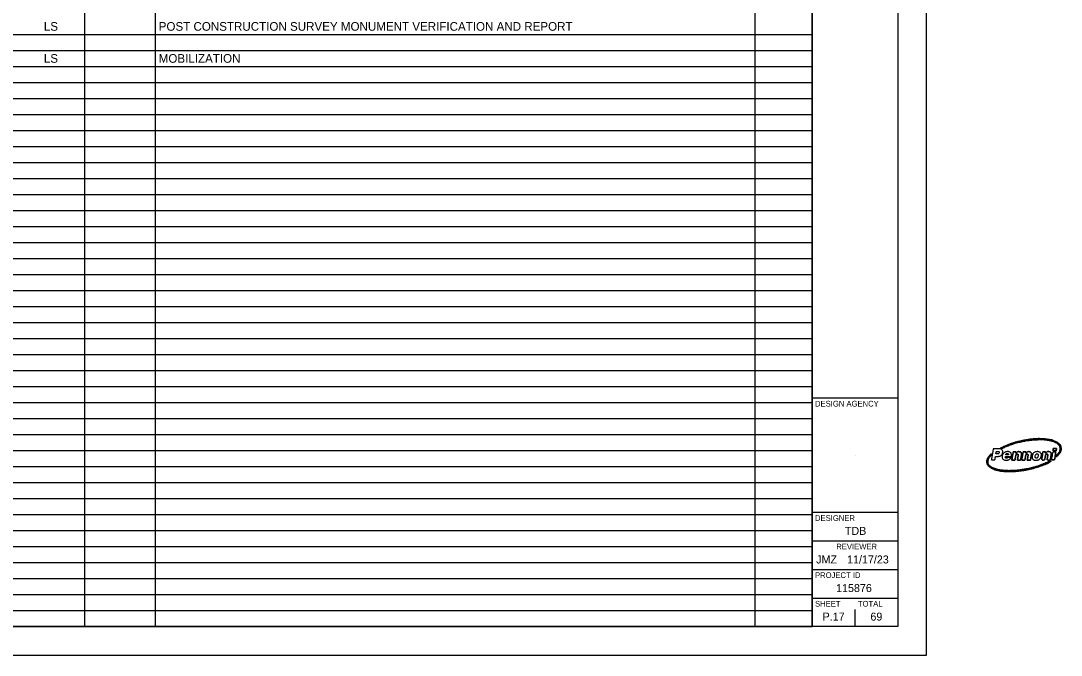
# Model space of a CAD drawing. Extents: x -50.3 to 36.4, y 0 to 22.5.
# Drawn here: x 18.16 to 36.36, y 0 to 11.1 of the extents above; entities that cross this region are included whole.
import ezdxf

# ---------------------------------------------------------------- set-up
doc = ezdxf.new("R2010")
doc.units = 0
for name, color, linetype in [('SH_Border', 7, 'Continuous'), ('SH_Cut_Line', 7, 'Continuous'), ('SH_Data', 7, 'Continuous'), ('SH_Text', 7, 'Continuous')]:
    doc.layers.add(name, color=color, linetype=linetype)

msp = doc.modelspace()

# ---------------------------------------------------------------- linework, layer by layer
at = {"layer": 'SH_Border'}
for p, q in [((32, 0.5), (32, 21.5)), ((32, 4.5), (33.5, 4.5)), ((35.435, 3.503), (35.385, 3.503)), ((32, 2.5), (33.5, 2.5)), ((32, 2), (33.5, 2)), ((32, 1.5), (33.5, 1.5)), ((32, 1), (33.5, 1))]:
    msp.add_line(p, q, dxfattribs=at)
msp.add_lwpolyline([(1.5, 21.5), (33.5, 21.5), (33.5, 0.5), (1.5, 0.5)], close=True, dxfattribs=at)
for points, degree in [([(35.294, 3.621), (35.301, 3.619), (35.307, 3.616), (35.313, 3.615), (35.315, 3.614), (35.318, 3.614), (35.32, 3.615), (35.349, 3.629), (35.377, 3.643), (35.406, 3.655), (35.447, 3.673), (35.49, 3.688), (35.532, 3.701), (35.574, 3.714), (35.617, 3.725), (35.66, 3.734), (35.7, 3.743), (35.74, 3.751), (35.78, 3.756), (35.812, 3.76), (35.844, 3.764), (35.876, 3.767), (35.901, 3.769), (35.927, 3.77), (35.952, 3.771), (36.007, 3.772), (36.062, 3.77), (36.116, 3.762), (36.146, 3.758), (36.175, 3.752), (36.204, 3.742), (36.239, 3.731), (36.273, 3.717), (36.301, 3.691), (36.316, 3.678), (36.328, 3.661), (36.333, 3.641), (36.338, 3.624), (36.339, 3.607), (36.336, 3.589), (36.333, 3.569), (36.323, 3.552), (36.311, 3.536), (36.298, 3.521), (36.284, 3.508), (36.27, 3.495), (36.268, 3.494), (36.267, 3.492), (36.266, 3.49), (36.265, 3.485), (36.264, 3.479), (36.263, 3.473), (36.263, 3.471), (36.262, 3.469), (36.262, 3.465), (36.286, 3.485), (36.308, 3.505), (36.327, 3.529), (36.336, 3.54), (36.344, 3.553), (36.349, 3.566), (36.356, 3.585), (36.356, 3.604), (36.354, 3.623), (36.35, 3.658), (36.334, 3.685), (36.308, 3.708), (36.284, 3.728), (36.256, 3.741), (36.227, 3.752), (36.19, 3.766), (36.152, 3.774), (36.112, 3.779), (36.078, 3.784), (36.042, 3.787), (36.007, 3.788), (35.951, 3.789), (35.895, 3.787), (35.838, 3.781), (35.807, 3.777), (35.777, 3.773), (35.746, 3.768), (35.701, 3.761), (35.656, 3.752), (35.611, 3.74), (35.551, 3.725), (35.492, 3.707), (35.433, 3.684), (35.392, 3.669), (35.352, 3.651), (35.313, 3.631), (35.307, 3.628), (35.301, 3.625), (35.294, 3.621)], 3), ([(35.294, 3.621), (35.301, 3.625), (35.307, 3.628), (35.313, 3.631), (35.352, 3.651), (35.392, 3.669), (35.433, 3.684), (35.492, 3.707), (35.551, 3.725), (35.611, 3.74), (35.656, 3.752), (35.701, 3.761), (35.746, 3.768), (35.777, 3.773), (35.807, 3.777), (35.838, 3.781), (35.895, 3.787), (35.951, 3.789), (36.007, 3.788), (36.042, 3.787), (36.078, 3.784), (36.112, 3.779), (36.152, 3.774), (36.19, 3.766), (36.227, 3.752), (36.256, 3.741), (36.284, 3.728), (36.308, 3.708), (36.334, 3.685), (36.35, 3.658), (36.354, 3.623), (36.356, 3.604), (36.356, 3.585), (36.349, 3.566), (36.344, 3.553), (36.336, 3.54), (36.327, 3.529), (36.308, 3.505), (36.286, 3.485), (36.262, 3.465), (36.262, 3.469), (36.263, 3.471), (36.263, 3.473), (36.264, 3.479), (36.265, 3.485), (36.266, 3.49), (36.267, 3.492), (36.268, 3.494), (36.27, 3.495), (36.284, 3.508), (36.298, 3.521), (36.311, 3.536), (36.323, 3.552), (36.333, 3.569), (36.336, 3.589), (36.339, 3.607), (36.338, 3.624), (36.333, 3.641), (36.328, 3.661), (36.316, 3.678), (36.301, 3.691), (36.273, 3.717), (36.239, 3.731), (36.204, 3.742), (36.175, 3.752), (36.146, 3.758), (36.116, 3.762), (36.062, 3.77), (36.007, 3.772), (35.952, 3.771), (35.927, 3.77), (35.901, 3.769), (35.876, 3.767), (35.844, 3.764), (35.812, 3.76), (35.78, 3.756), (35.74, 3.751), (35.7, 3.743), (35.66, 3.734), (35.617, 3.725), (35.574, 3.714), (35.532, 3.701), (35.49, 3.688), (35.447, 3.673), (35.406, 3.655), (35.377, 3.643), (35.349, 3.629), (35.32, 3.615), (35.318, 3.614), (35.315, 3.614), (35.313, 3.615), (35.307, 3.616), (35.301, 3.619), (35.294, 3.621)], 3), ([(36.182, 3.392), (36.182, 3.392), (36.182, 3.393), (36.182, 3.393), (36.172, 3.393), (36.162, 3.393), (36.152, 3.393), (36.15, 3.393), (36.147, 3.392), (36.145, 3.391), (36.107, 3.372), (36.069, 3.355), (36.03, 3.34), (35.972, 3.317), (35.913, 3.298), (35.853, 3.283), (35.81, 3.271), (35.767, 3.262), (35.723, 3.254), (35.698, 3.25), (35.673, 3.246), (35.648, 3.242), (35.623, 3.239), (35.597, 3.236), (35.571, 3.234), (35.547, 3.232), (35.523, 3.23), (35.499, 3.23), (35.471, 3.229), (35.443, 3.228), (35.414, 3.229), (35.383, 3.231), (35.352, 3.233), (35.322, 3.236), (35.284, 3.24), (35.246, 3.248), (35.209, 3.259), (35.178, 3.269), (35.148, 3.282), (35.121, 3.302), (35.104, 3.314), (35.09, 3.329), (35.081, 3.348), (35.069, 3.374), (35.07, 3.4), (35.081, 3.427), (35.09, 3.45), (35.104, 3.47), (35.121, 3.488), (35.126, 3.494), (35.132, 3.5), (35.132, 3.509), (35.132, 3.514), (35.134, 3.52), (35.135, 3.526), (35.134, 3.525), (35.133, 3.525), (35.132, 3.524), (35.123, 3.514), (35.113, 3.505), (35.104, 3.494), (35.084, 3.472), (35.068, 3.448), (35.06, 3.419), (35.055, 3.402), (35.054, 3.385), (35.057, 3.368), (35.062, 3.341), (35.076, 3.319), (35.096, 3.301), (35.119, 3.28), (35.146, 3.266), (35.174, 3.254), (35.221, 3.235), (35.27, 3.225), (35.321, 3.219), (35.351, 3.216), (35.382, 3.214), (35.413, 3.212), (35.456, 3.211), (35.498, 3.211), (35.54, 3.215), (35.575, 3.217), (35.609, 3.221), (35.643, 3.225), (35.674, 3.229), (35.704, 3.234), (35.735, 3.239), (35.789, 3.249), (35.843, 3.261), (35.896, 3.276), (35.941, 3.289), (35.986, 3.304), (36.029, 3.321), (36.073, 3.338), (36.115, 3.356), (36.156, 3.377), (36.165, 3.382), (36.173, 3.387), (36.182, 3.392)], 3), ([(36.182, 3.392), (36.173, 3.387), (36.165, 3.382), (36.156, 3.377), (36.115, 3.356), (36.073, 3.338), (36.029, 3.321), (35.986, 3.304), (35.941, 3.289), (35.896, 3.276), (35.843, 3.261), (35.789, 3.249), (35.735, 3.239), (35.704, 3.234), (35.674, 3.229), (35.643, 3.225), (35.609, 3.221), (35.575, 3.217), (35.54, 3.215), (35.498, 3.211), (35.456, 3.211), (35.413, 3.212), (35.382, 3.214), (35.351, 3.216), (35.321, 3.219), (35.27, 3.225), (35.221, 3.235), (35.174, 3.254), (35.146, 3.266), (35.119, 3.28), (35.096, 3.301), (35.076, 3.319), (35.062, 3.341), (35.057, 3.368), (35.054, 3.385), (35.055, 3.402), (35.06, 3.419), (35.068, 3.448), (35.084, 3.472), (35.104, 3.494), (35.113, 3.505), (35.123, 3.514), (35.132, 3.524), (35.133, 3.525), (35.134, 3.525), (35.135, 3.526), (35.134, 3.52), (35.132, 3.514), (35.132, 3.509), (35.132, 3.5), (35.126, 3.494), (35.121, 3.488), (35.104, 3.47), (35.09, 3.45), (35.081, 3.427), (35.07, 3.4), (35.069, 3.374), (35.081, 3.348), (35.09, 3.329), (35.104, 3.314), (35.121, 3.302), (35.148, 3.282), (35.178, 3.269), (35.209, 3.259), (35.246, 3.248), (35.284, 3.24), (35.322, 3.236), (35.352, 3.233), (35.383, 3.231), (35.414, 3.229), (35.443, 3.228), (35.471, 3.229), (35.499, 3.23), (35.523, 3.23), (35.547, 3.232), (35.571, 3.234), (35.597, 3.236), (35.623, 3.239), (35.648, 3.242), (35.673, 3.246), (35.698, 3.25), (35.723, 3.254), (35.767, 3.262), (35.81, 3.271), (35.853, 3.283), (35.913, 3.298), (35.972, 3.317), (36.03, 3.34), (36.069, 3.355), (36.107, 3.372), (36.145, 3.391), (36.147, 3.392), (36.15, 3.393), (36.152, 3.393), (36.162, 3.393), (36.172, 3.393), (36.182, 3.393), (36.182, 3.393), (36.182, 3.392), (36.182, 3.392)], 3), ([(35.305, 3.602), (35.293, 3.608), (35.279, 3.61), (35.266, 3.61), (35.234, 3.611), (35.202, 3.61), (35.171, 3.61), (35.168, 3.61), (35.167, 3.61), (35.167, 3.608), (35.163, 3.586), (35.16, 3.565), (35.156, 3.543), (35.15, 3.509), (35.144, 3.474), (35.138, 3.439), (35.136, 3.432), (35.135, 3.424), (35.134, 3.417)], 3), ([(35.134, 3.417), (35.135, 3.417), (35.135, 3.417), (35.136, 3.417), (35.155, 3.417), (35.175, 3.417), (35.194, 3.417), (35.197, 3.417), (35.197, 3.418), (35.197, 3.42), (35.199, 3.431), (35.201, 3.442), (35.203, 3.454), (35.204, 3.461), (35.206, 3.469), (35.207, 3.477)], 3), ([(35.207, 3.477), (35.215, 3.477), (35.222, 3.477), (35.229, 3.477), (35.242, 3.477), (35.254, 3.477), (35.267, 3.48), (35.284, 3.483), (35.299, 3.49), (35.311, 3.502), (35.326, 3.518), (35.332, 3.537), (35.332, 3.559), (35.333, 3.578), (35.324, 3.593), (35.305, 3.602)], 3), ([(35.215, 3.522), (35.217, 3.536), (35.22, 3.55), (35.222, 3.563), (35.222, 3.564), (35.224, 3.565), (35.224, 3.565), (35.236, 3.565), (35.247, 3.567), (35.259, 3.563), (35.269, 3.56), (35.273, 3.554), (35.271, 3.543)], 3), ([(35.271, 3.543), (35.268, 3.531), (35.26, 3.523), (35.247, 3.522), (35.237, 3.522), (35.226, 3.522), (35.215, 3.522)], 3), ([(35.487, 3.508), (35.483, 3.533), (35.47, 3.55), (35.446, 3.557), (35.433, 3.562), (35.419, 3.562), (35.406, 3.561), (35.384, 3.558), (35.365, 3.549), (35.349, 3.532), (35.335, 3.517), (35.327, 3.5), (35.325, 3.479), (35.322, 3.45), (35.334, 3.426), (35.363, 3.417), (35.379, 3.412), (35.395, 3.411), (35.412, 3.414), (35.429, 3.416), (35.446, 3.422), (35.46, 3.434), (35.467, 3.441), (35.474, 3.449), (35.478, 3.459)], 3), ([(35.478, 3.459), (35.461, 3.459), (35.444, 3.459), (35.427, 3.458), (35.426, 3.458), (35.425, 3.457), (35.424, 3.457), (35.42, 3.454), (35.416, 3.45), (35.411, 3.448), (35.395, 3.442), (35.378, 3.451), (35.379, 3.47), (35.379, 3.474), (35.38, 3.475), (35.384, 3.475), (35.416, 3.475), (35.448, 3.475), (35.48, 3.475), (35.482, 3.475), (35.484, 3.475), (35.486, 3.475)], 3), ([(35.385, 3.503), (35.386, 3.515), (35.395, 3.525), (35.408, 3.527), (35.414, 3.528), (35.42, 3.528), (35.425, 3.525), (35.433, 3.521), (35.436, 3.513), (35.435, 3.503)], 3), ([(35.486, 3.475), (35.488, 3.486), (35.489, 3.497), (35.487, 3.508)], 2), ([(35.493, 3.416), (35.493, 3.415), (35.494, 3.415), (35.494, 3.415), (35.511, 3.415), (35.528, 3.415), (35.545, 3.415), (35.548, 3.415), (35.548, 3.416), (35.549, 3.418), (35.55, 3.426), (35.551, 3.435), (35.553, 3.443), (35.556, 3.46), (35.559, 3.478), (35.563, 3.495), (35.565, 3.505), (35.569, 3.513), (35.579, 3.515), (35.592, 3.519), (35.606, 3.516), (35.604, 3.497), (35.602, 3.482), (35.599, 3.468), (35.597, 3.454), (35.595, 3.441), (35.592, 3.428), (35.59, 3.416), (35.591, 3.415), (35.591, 3.415), (35.592, 3.415), (35.609, 3.415), (35.626, 3.415), (35.643, 3.415), (35.645, 3.415), (35.646, 3.416), (35.646, 3.419), (35.65, 3.442), (35.654, 3.466), (35.659, 3.49), (35.661, 3.502), (35.663, 3.515), (35.661, 3.527), (35.659, 3.543), (35.65, 3.554), (35.634, 3.558), (35.612, 3.564), (35.593, 3.56), (35.576, 3.545), (35.572, 3.542), (35.568, 3.538), (35.564, 3.535), (35.565, 3.542), (35.567, 3.549), (35.568, 3.557), (35.552, 3.557), (35.535, 3.557), (35.519, 3.556), (35.518, 3.556), (35.517, 3.555), (35.517, 3.554), (35.516, 3.55), (35.515, 3.545), (35.514, 3.541), (35.509, 3.511), (35.504, 3.48), (35.498, 3.45), (35.496, 3.438), (35.495, 3.427), (35.493, 3.416)], 3), ([(35.493, 3.416), (35.495, 3.427), (35.496, 3.438), (35.498, 3.45), (35.504, 3.48), (35.509, 3.511), (35.514, 3.541), (35.515, 3.545), (35.516, 3.55), (35.517, 3.554), (35.517, 3.555), (35.518, 3.556), (35.519, 3.556), (35.535, 3.557), (35.552, 3.557), (35.568, 3.557), (35.567, 3.549), (35.565, 3.542), (35.564, 3.535), (35.568, 3.538), (35.572, 3.542), (35.576, 3.545), (35.593, 3.56), (35.612, 3.564), (35.634, 3.558), (35.65, 3.554), (35.659, 3.543), (35.661, 3.527), (35.663, 3.515), (35.661, 3.502), (35.659, 3.49), (35.654, 3.466), (35.65, 3.442), (35.646, 3.419), (35.646, 3.416), (35.645, 3.415), (35.643, 3.415), (35.626, 3.415), (35.609, 3.415), (35.592, 3.415), (35.591, 3.415), (35.591, 3.415), (35.59, 3.416), (35.592, 3.428), (35.595, 3.441), (35.597, 3.454), (35.599, 3.468), (35.602, 3.482), (35.604, 3.497), (35.606, 3.516), (35.592, 3.519), (35.579, 3.515), (35.569, 3.513), (35.565, 3.505), (35.563, 3.495), (35.559, 3.478), (35.556, 3.46), (35.553, 3.443), (35.551, 3.435), (35.55, 3.426), (35.549, 3.418), (35.548, 3.416), (35.548, 3.415), (35.545, 3.415), (35.528, 3.415), (35.511, 3.415), (35.494, 3.415), (35.494, 3.415), (35.493, 3.415), (35.493, 3.416)], 3), ([(35.666, 3.416), (35.666, 3.415), (35.666, 3.415), (35.667, 3.415), (35.684, 3.415), (35.701, 3.415), (35.719, 3.415), (35.72, 3.415), (35.721, 3.417), (35.721, 3.418), (35.725, 3.435), (35.727, 3.452), (35.731, 3.469), (35.732, 3.479), (35.734, 3.49), (35.737, 3.5), (35.741, 3.513), (35.753, 3.519), (35.766, 3.516), (35.772, 3.515), (35.775, 3.511), (35.776, 3.505), (35.777, 3.502), (35.777, 3.499), (35.777, 3.496), (35.775, 3.485), (35.773, 3.473), (35.771, 3.462), (35.768, 3.447), (35.766, 3.431), (35.763, 3.416), (35.763, 3.415), (35.764, 3.415), (35.764, 3.415), (35.781, 3.415), (35.799, 3.415), (35.816, 3.415), (35.817, 3.415), (35.819, 3.417), (35.819, 3.418), (35.823, 3.441), (35.827, 3.463), (35.831, 3.485), (35.833, 3.497), (35.835, 3.509), (35.835, 3.522), (35.835, 3.537), (35.829, 3.55), (35.813, 3.556), (35.793, 3.564), (35.773, 3.562), (35.755, 3.55), (35.749, 3.545), (35.743, 3.54), (35.737, 3.535), (35.739, 3.543), (35.74, 3.549), (35.741, 3.557), (35.724, 3.557), (35.709, 3.557), (35.693, 3.557), (35.69, 3.557), (35.69, 3.555), (35.69, 3.553), (35.685, 3.529), (35.681, 3.505), (35.677, 3.481), (35.673, 3.46), (35.669, 3.438), (35.666, 3.416)], 3), ([(35.666, 3.416), (35.669, 3.438), (35.673, 3.46), (35.677, 3.481), (35.681, 3.505), (35.685, 3.529), (35.69, 3.553), (35.69, 3.555), (35.69, 3.557), (35.693, 3.557), (35.709, 3.557), (35.724, 3.557), (35.741, 3.557), (35.74, 3.549), (35.739, 3.543), (35.737, 3.535), (35.743, 3.54), (35.749, 3.545), (35.755, 3.55), (35.773, 3.562), (35.793, 3.564), (35.813, 3.556), (35.829, 3.55), (35.835, 3.537), (35.835, 3.522), (35.835, 3.509), (35.833, 3.497), (35.831, 3.485), (35.827, 3.463), (35.823, 3.441), (35.819, 3.418), (35.819, 3.417), (35.817, 3.415), (35.816, 3.415), (35.799, 3.415), (35.781, 3.415), (35.764, 3.415), (35.764, 3.415), (35.763, 3.415), (35.763, 3.416), (35.766, 3.431), (35.768, 3.447), (35.771, 3.462), (35.773, 3.473), (35.775, 3.485), (35.777, 3.496), (35.777, 3.499), (35.777, 3.502), (35.776, 3.505), (35.775, 3.511), (35.772, 3.515), (35.766, 3.516), (35.753, 3.519), (35.741, 3.513), (35.737, 3.5), (35.734, 3.49), (35.732, 3.479), (35.731, 3.469), (35.727, 3.452), (35.725, 3.435), (35.721, 3.418), (35.721, 3.417), (35.72, 3.415), (35.719, 3.415), (35.701, 3.415), (35.684, 3.415), (35.667, 3.415), (35.666, 3.415), (35.666, 3.415), (35.666, 3.416)], 3), ([(36.009, 3.508), (36.007, 3.53), (35.996, 3.545), (35.976, 3.554), (35.957, 3.562), (35.937, 3.562), (35.917, 3.558), (35.893, 3.553), (35.873, 3.541), (35.86, 3.52), (35.859, 3.518), (35.858, 3.515), (35.857, 3.513), (35.856, 3.511), (35.855, 3.509), (35.854, 3.507), (35.849, 3.496), (35.846, 3.484), (35.846, 3.472), (35.846, 3.47), (35.846, 3.467), (35.846, 3.465), (35.846, 3.457), (35.848, 3.45), (35.851, 3.444), (35.851, 3.443), (35.852, 3.441), (35.852, 3.44), (35.853, 3.439), (35.853, 3.438), (35.854, 3.437), (35.856, 3.434), (35.859, 3.43), (35.863, 3.427), (35.864, 3.426), (35.867, 3.424), (35.869, 3.423), (35.869, 3.422), (35.87, 3.422), (35.87, 3.422), (35.872, 3.421), (35.873, 3.42), (35.874, 3.42), (35.876, 3.419), (35.878, 3.418), (35.88, 3.417), (35.891, 3.412), (35.902, 3.411), (35.914, 3.41)], 3), ([(35.902, 3.471), (35.902, 3.487), (35.905, 3.501), (35.914, 3.513), (35.919, 3.519), (35.926, 3.523), (35.934, 3.523), (35.943, 3.523), (35.949, 3.52), (35.951, 3.511), (35.952, 3.505), (35.953, 3.498), (35.952, 3.491)], 3), ([(35.952, 3.491), (35.952, 3.481), (35.949, 3.471), (35.944, 3.462), (35.938, 3.452), (35.928, 3.447), (35.917, 3.449), (35.911, 3.45), (35.906, 3.453), (35.904, 3.459), (35.903, 3.464), (35.902, 3.469), (35.902, 3.471)], 3), ([(35.914, 3.41), (35.922, 3.411), (35.929, 3.412), (35.936, 3.413), (35.955, 3.416), (35.972, 3.425), (35.985, 3.439), (36.002, 3.459), (36.01, 3.482), (36.009, 3.508)], 3), ([(36.036, 3.556), (36.028, 3.509), (36.02, 3.462), (36.012, 3.415), (36.031, 3.415), (36.049, 3.415), (36.067, 3.415), (36.07, 3.43), (36.072, 3.444), (36.075, 3.458), (36.077, 3.471), (36.079, 3.484), (36.082, 3.496), (36.085, 3.51), (36.095, 3.517), (36.108, 3.517), (36.117, 3.516), (36.122, 3.511), (36.123, 3.503), (36.123, 3.5), (36.123, 3.497), (36.123, 3.494), (36.119, 3.475), (36.116, 3.456), (36.113, 3.437), (36.112, 3.43), (36.11, 3.423), (36.109, 3.415), (36.128, 3.415), (36.146, 3.415), (36.164, 3.415), (36.165, 3.417), (36.165, 3.418), (36.165, 3.419), (36.169, 3.44), (36.173, 3.462), (36.176, 3.483), (36.179, 3.497), (36.182, 3.51), (36.181, 3.525), (36.18, 3.541), (36.171, 3.553), (36.155, 3.558), (36.13, 3.565), (36.108, 3.559), (36.09, 3.541), (36.088, 3.539), (36.086, 3.537), (36.084, 3.535), (36.084, 3.535), (36.084, 3.535), (36.083, 3.536), (36.085, 3.542), (36.086, 3.549), (36.087, 3.556), (36.07, 3.556), (36.053, 3.556), (36.036, 3.556)], 3), ([(36.036, 3.556), (36.053, 3.556), (36.07, 3.556), (36.087, 3.556), (36.086, 3.549), (36.085, 3.542), (36.083, 3.536), (36.084, 3.535), (36.084, 3.535), (36.084, 3.535), (36.086, 3.537), (36.088, 3.539), (36.09, 3.541), (36.108, 3.559), (36.13, 3.565), (36.155, 3.558), (36.171, 3.553), (36.18, 3.541), (36.181, 3.525), (36.182, 3.51), (36.179, 3.497), (36.176, 3.483), (36.173, 3.462), (36.169, 3.44), (36.165, 3.419), (36.165, 3.418), (36.165, 3.417), (36.164, 3.415), (36.146, 3.415), (36.128, 3.415), (36.109, 3.415), (36.11, 3.423), (36.112, 3.43), (36.113, 3.437), (36.116, 3.456), (36.119, 3.475), (36.123, 3.494), (36.123, 3.497), (36.123, 3.5), (36.123, 3.503), (36.122, 3.511), (36.117, 3.516), (36.108, 3.517), (36.095, 3.517), (36.085, 3.51), (36.082, 3.496), (36.079, 3.484), (36.077, 3.471), (36.075, 3.458), (36.072, 3.444), (36.07, 3.43), (36.067, 3.415), (36.049, 3.415), (36.031, 3.415), (36.012, 3.415), (36.02, 3.462), (36.028, 3.509), (36.036, 3.556)], 3), ([(36.239, 3.417), (36.221, 3.417), (36.203, 3.417), (36.184, 3.417), (36.192, 3.464), (36.2, 3.51), (36.208, 3.557), (36.227, 3.557), (36.245, 3.557), (36.264, 3.557), (36.255, 3.51), (36.247, 3.464), (36.239, 3.417)], 3), ([(36.239, 3.417), (36.247, 3.464), (36.255, 3.51), (36.264, 3.557), (36.245, 3.557), (36.227, 3.557), (36.208, 3.557), (36.2, 3.51), (36.192, 3.464), (36.184, 3.417), (36.203, 3.417), (36.221, 3.417), (36.239, 3.417)], 3), ([(36.274, 3.615), (36.272, 3.603), (36.27, 3.591), (36.267, 3.578), (36.267, 3.577), (36.265, 3.576), (36.264, 3.576), (36.247, 3.576), (36.23, 3.576), (36.212, 3.576), (36.213, 3.586), (36.215, 3.595), (36.217, 3.604), (36.217, 3.606), (36.218, 3.609), (36.218, 3.611), (36.218, 3.615), (36.219, 3.615), (36.223, 3.615), (36.238, 3.615), (36.254, 3.615), (36.269, 3.615), (36.271, 3.615), (36.272, 3.615), (36.274, 3.615)], 3), ([(36.274, 3.615), (36.272, 3.615), (36.271, 3.615), (36.269, 3.615), (36.254, 3.615), (36.238, 3.615), (36.223, 3.615), (36.219, 3.615), (36.218, 3.615), (36.218, 3.611), (36.218, 3.609), (36.217, 3.606), (36.217, 3.604), (36.215, 3.595), (36.213, 3.586), (36.212, 3.576), (36.23, 3.576), (36.247, 3.576), (36.264, 3.576), (36.265, 3.576), (36.267, 3.577), (36.267, 3.578), (36.27, 3.591), (36.272, 3.603), (36.274, 3.615)], 3)]:
    msp.add_open_spline(points, degree=degree, dxfattribs=at)
at = {"layer": 'SH_Cut_Line'}
msp.add_lwpolyline([(0, 0), (34, 0), (34, 22), (0, 22)], close=True, dxfattribs=at)
at = {"layer": 'SH_Data'}
for p, q in [((19.27, 21.5), (19.27, 0.502)), ((20.506, 21.5), (20.506, 0.502)), ((30.997, 21.5), (30.997, 0.502)), ((32.001, 21.5), (32.001, 0.502)), ((1.5, 10.861), (32.001, 10.861)), ((1.5, 10.581), (32.001, 10.581)), ((1.5, 10.301), (32.001, 10.301)), ((1.5, 10.021), (32.001, 10.021)), ((1.5, 9.741), (32.001, 9.741)), ((1.5, 9.461), (32.001, 9.461)), ((1.5, 9.181), (32.001, 9.181)), ((1.5, 8.901), (32.001, 8.901)), ((1.5, 8.621), (32.001, 8.621)), ((1.5, 8.341), (32.001, 8.341)), ((1.5, 8.061), (32.001, 8.061)), ((1.5, 7.781), (32.001, 7.781)), ((1.5, 7.501), (32.001, 7.501)), ((1.5, 7.221), (32.001, 7.221)), ((1.5, 6.941), (32.001, 6.941)), ((1.5, 6.661), (32.001, 6.661)), ((1.5, 6.381), (32.001, 6.381)), ((1.5, 6.101), (32.001, 6.101)), ((1.5, 5.821), (32.001, 5.821)), ((1.5, 5.541), (32.001, 5.541)), ((1.5, 5.261), (32.001, 5.261)), ((1.5, 4.981), (32.001, 4.981)), ((1.5, 4.701), (32.001, 4.701)), ((1.5, 4.421), (32.001, 4.421)), ((1.5, 4.141), (32.001, 4.141)), ((1.5, 3.861), (32.001, 3.861)), ((1.5, 3.581), (32.001, 3.581)), ((32.75, 3.5), (32.75, 3.5)), ((1.5, 3.301), (32.001, 3.301)), ((1.5, 3.021), (32.001, 3.021)), ((1.5, 2.741), (32.001, 2.741)), ((1.5, 2.461), (32.001, 2.461)), ((1.5, 2.182), (32.001, 2.182)), ((1.5, 1.902), (32.001, 1.902)), ((1.5, 1.622), (32.001, 1.622)), ((1.5, 1.342), (32.001, 1.342)), ((1.5, 1.062), (32.001, 1.062)), ((1.5, 0.782), (32.001, 0.782)), ((32.75, 0.5), (32.75, 0.8)), ((32.375, 0.675), (32.375, 0.675)), ((1.5, 0.502), (32.001, 0.502))]:
    msp.add_line(p, q, dxfattribs=at)

# ---------------------------------------------------------------- texts
for s, height, p in [('DESIGN AGENCY', 0.1, (32.05, 4.35)), ('DESIGNER', 0.1, (32.05, 2.35)), ('TDB', 0.14, (32.573, 2.105)), ('REVIEWER', 0.1, (32.422, 1.85)), ('JMZ', 0.14, (32.071, 1.605)), ('11/17/23', 0.14, (32.611, 1.605)), ('PROJECT ID', 0.1, (32.05, 1.35)), ('115876', 0.14, (32.419, 1.105)), ('SHEET', 0.1, (32.05, 0.85)), ('TOTAL', 0.1, (32.8, 0.85)), ('P.17', 0.14, (32.183, 0.605)), ('69', 0.14, (33.019, 0.605))]:
    msp.add_text(s, height=height, dxfattribs=at).set_placement(p)
at = {"layer": 'SH_Text'}
for s, height, p in [('LS', 0.1515, (18.562, 10.925)), ('POST CONSTRUCTION SURVEY MONUMENT VERIFICATION AND REPORT', 0.15152, (20.571, 10.925)), ('LS', 0.1515, (18.562, 10.365)), ('MOBILIZATION', 0.15152, (20.571, 10.365))]:
    msp.add_text(s, height=height, dxfattribs=at).set_placement(p)

doc.saveas('drawing.dxf')
